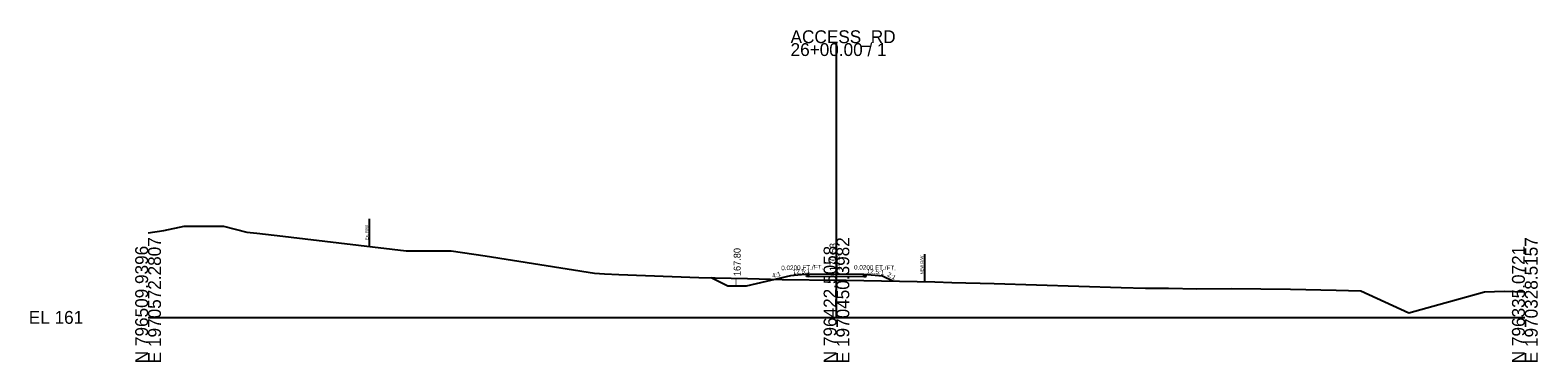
# Model space of a CAD drawing. Extents: x 27306 to 1891059, y 5381 to 776288.
# Drawn here: x 28306 to 28634.5, y 7380.7 to 7453.1 of the extents above; entities that cross this region are included whole.
import ezdxf

# ---------------------------------------------------------------- set-up
doc = ezdxf.new("R2010")
doc.units = 0
for name, color, linetype in [('RD_EX_BldgApp', 7, 'Continuous'), ('RD_EX_H2O_BlueLn', 7, 'Continuous'), ('RD_EX_RailRoad', 7, 'Continuous'), ('RD_HC_Cl', 7, 'Continuous'), ('RD_HC_Data', 7, 'Continuous'), ('RD_HC_Data_Tic', 7, 'Continuous'), ('RD_HC_TX_Sta50', 7, 'Continuous'), ('RD_PD_ALT2_CL', 7, 'Continuous'), ('RD_PD_ALT3_CL', 7, 'Continuous'), ('RD_PD_ALT5_CL', 7, 'Continuous'), ('RD_PD_Final_Cl', 7, 'Continuous'), ('RD_PD_Final_TrvlWay', 7, 'Continuous'), ('RD_PD_MedBWall', 7, 'Continuous'), ('RD_TX_RoadID', 7, 'Continuous')]:
    doc.layers.add(name, color=color, linetype=linetype)

msp = doc.modelspace()

# ---------------------------------------------------------------- linework, layer by layer
at = {"layer": 'RD_EX_H2O_BlueLn'}
for p, q in [((28475.65, 7399.84), (28471.65, 7399.52)), ((28487.65, 7399.84), (28491.65, 7399.52))]:
    msp.add_line(p, q, dxfattribs=at)
at = {"layer": 'RD_EX_RailRoad'}
for p, q in [((28475.15, 7399.58), (28475.65, 7399.59)), ((28475.15, 7399.33), (28475.15, 7399.58)), ((28475.65, 7399.34), (28475.15, 7399.33)), ((28475.65, 7399.59), (28475.65, 7399.84)), ((28475.65, 7399.34), (28481.65, 7399.46)), ((28481.65, 7399.46), (28487.65, 7399.34)), ((28487.65, 7399.59), (28487.65, 7399.84)), ((28488.15, 7399.58), (28487.65, 7399.59)), ((28487.65, 7399.34), (28488.15, 7399.33)), ((28488.15, 7399.33), (28488.15, 7399.58))]:
    msp.add_line(p, q, dxfattribs=at)
at = {"layer": 'RD_HC_Cl'}
for p, q in [((28481.65, 7390.44), (28481.65, 7450.24)), ((28331.65, 7390.44), (28481.65, 7390.44)), ((28481.65, 7390.44), (28631.65, 7390.44))]:
    msp.add_line(p, q, dxfattribs=at)
at = {"layer": 'RD_PD_ALT5_CL'}
for p, q in [((28458.01, 7397.24), (28454.35, 7399.07)), ((28471.65, 7399.52), (28462.01, 7397.24)), ((28491.65, 7399.52), (28493.93, 7398.38)), ((28462.01, 7397.24), (28458.01, 7397.24))]:
    msp.add_line(p, q, dxfattribs=at)
at = {"layer": 'RD_PD_Final_Cl'}
msp.add_lwpolyline([(28331.65, 7408.91), (28335.06, 7409.41), (28339.52, 7410.37), (28348.12, 7410.37), (28353.15, 7408.99), (28355.37, 7408.83), (28361.04, 7408.15), (28362.83, 7407.95), (28387.92, 7404.97), (28397.73, 7404.98), (28405.13, 7403.85), (28428.95, 7400.11), (28431.07, 7399.92), (28434.26, 7399.8), (28451.63, 7399.12), (28462.23, 7398.92), (28469.83, 7398.72), (28481.65, 7398.59), (28483.73, 7398.57), (28503.11, 7398.2), (28506.76, 7398.08), (28516.01, 7397.8), (28543.67, 7396.97), (28549, 7396.8), (28554.04, 7396.79), (28560.19, 7396.69), (28567.67, 7396.75), (28580.59, 7396.63), (28590.53, 7396.38), (28595.95, 7396.23), (28606.4, 7391.42), (28622.84, 7396.02), (28627.22, 7396.13), (28631.65, 7395.98)], dxfattribs=at)
at = {"layer": 'RD_PD_Final_TrvlWay'}
msp.add_line((28379.86, 7411.91), (28379.86, 7405.91), dxfattribs=at)
at = {"layer": 'RD_PD_MedBWall'}
for p, q in [((28475.65, 7399.84), (28481.65, 7399.96)), ((28481.65, 7399.96), (28487.65, 7399.84))]:
    msp.add_line(p, q, dxfattribs=at)
at = {"layer": 'RD_TX_RoadID'}
msp.add_line((28500.87, 7404.25), (28500.87, 7398.25), dxfattribs=at)

# ---------------------------------------------------------------- texts
at = {"layer": 'RD_EX_BldgApp'}
msp.add_text('169.16', height=0.8, rotation=90, dxfattribs=at).set_placement((28482.35, 7400.62))
at = {"layer": 'RD_HC_Cl'}
for s, p in [('ACCESS_RD', (28471.65, 7450.24)), ('26+00.00 / 1', (28471.65, 7447.44)), ('EL 161', (28305.65, 7389.04))]:
    msp.add_text(s, height=2.8, dxfattribs=at).set_placement(p)
for s, p in [('N 796509.9396', (28331.65, 7380.44)), ('E 1970572.2807', (28334.45, 7380.44)), ('N 796422.5058', (28481.65, 7380.44)), ('E 1970450.3982', (28484.45, 7380.44)), ('N 796335.0721', (28631.65, 7380.44)), ('E 1970328.5157', (28634.45, 7380.44))]:
    msp.add_text(s, height=2.8, rotation=90, dxfattribs=at).set_placement(p)
at = {"layer": 'RD_HC_Data'}
msp.add_text(' 170.53', height=1.5, rotation=90, dxfattribs=at).set_placement((28481.65, 7399.96))
at = {"layer": 'RD_HC_Data_Tic'}
for rotation, p in [(4.5739, (28472.15, 7399.81)), (355.4261, (28488.19, 7400.05))]:
    msp.add_text('12.5:1', height=1, rotation=rotation, dxfattribs=at).set_placement(p)
at = {"layer": 'RD_HC_TX_Sta50'}
for s, rotation, p in [('0.0200 FT./FT.', 1.1458, (28469.63, 7400.72)), ('0.0200 FT./FT.', 358.8542, (28485.47, 7400.89)), ('4:1', 15.6461, (28467.77, 7398.99)), ('2:1', 331.3922, (28492.59, 7399.5))]:
    msp.add_text(s, height=1, rotation=rotation, dxfattribs=at).set_placement(p)
at = {"layer": 'RD_PD_ALT2_CL'}
msp.add_text('167.80', height=1.5, rotation=90, dxfattribs=at).set_placement((28460.76, 7399.44))
at = {"layer": 'RD_PD_ALT3_CL'}
msp.add_text('L', height=1.5, dxfattribs=at).set_placement((28459.51, 7397.24))
at = {"layer": 'RD_PD_Final_TrvlWay'}
msp.add_text('Ex. R/W ', height=0.65, rotation=90, dxfattribs=at).set_placement((28379.61, 7407.29))
at = {"layer": 'RD_TX_RoadID'}
msp.add_text('NEW R/W ', height=0.65, rotation=90, dxfattribs=at).set_placement((28500.6, 7399.81))

doc.saveas('drawing.dxf')
